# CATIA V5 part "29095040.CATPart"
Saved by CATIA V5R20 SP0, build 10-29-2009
Part number: 29095040
Definition: NONE
Nomenclature: 29095040
Source: Unknown
Description: 29095040
Bounding box of the stored display mesh (mm): x -20 to 44.548, y -61.5 to 96.048, z -51.5 to 51.5
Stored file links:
  C:\Users\Utente\Desktop\IO LAVORO\3D X SITO CF\X SITO\PLASTICA\RF1\29095040.CATPart
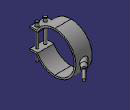
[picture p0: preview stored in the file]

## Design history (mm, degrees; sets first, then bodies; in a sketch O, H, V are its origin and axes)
Body1 "29095040" (main body)
  Solid1: solid without history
